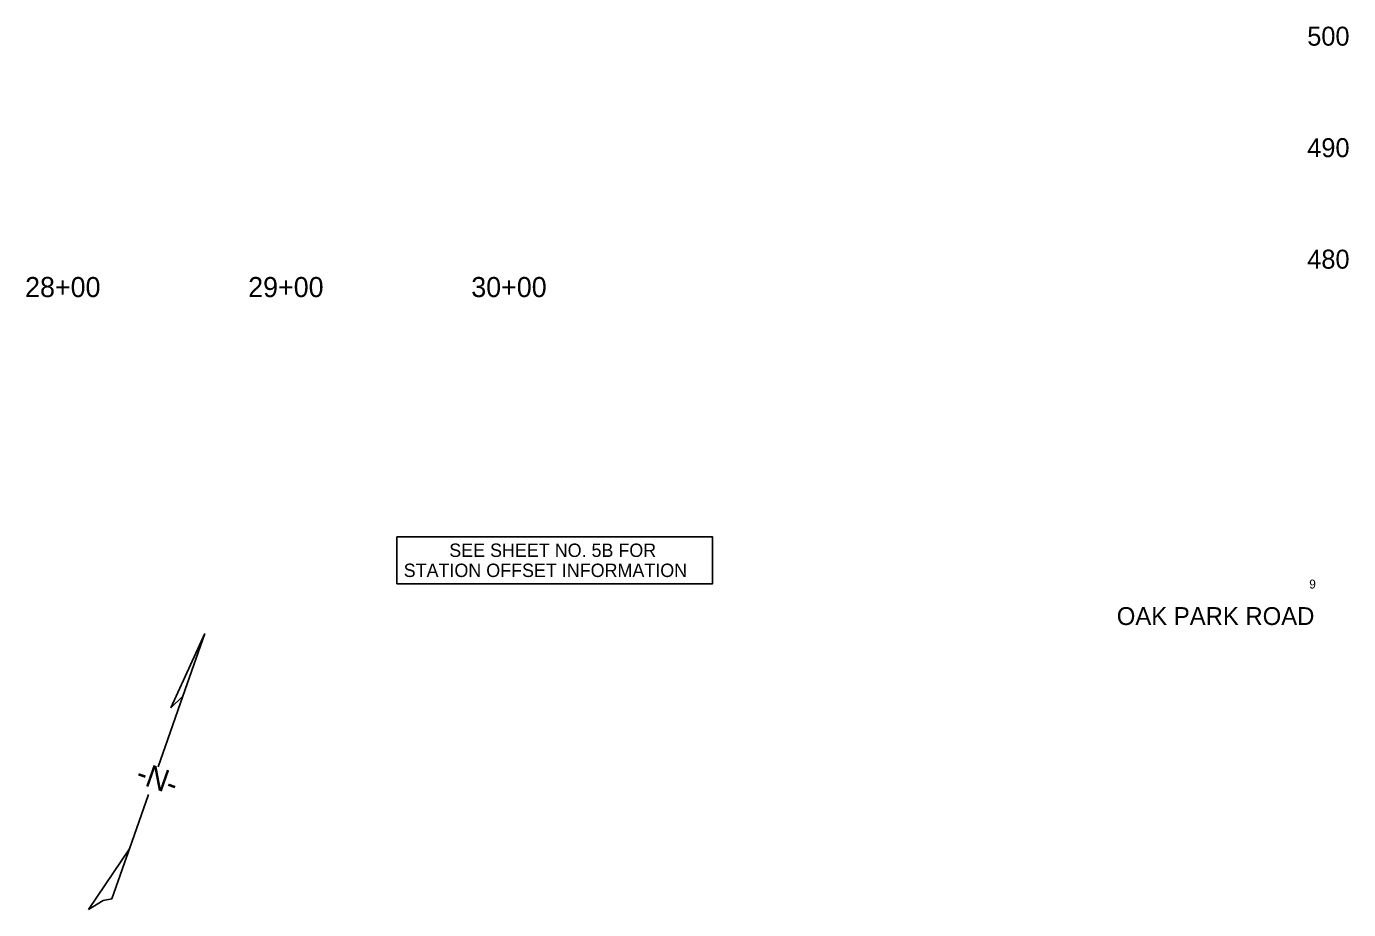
# Model space of a CAD drawing. Extents: x 1964377 to 1966966, y 1116414 to 1123213.
# Drawn here: x 1966357 to 1966950, y 1120739 to 1121135 of the extents above; entities that cross this region are included whole.
import ezdxf

# ---------------------------------------------------------------- set-up
doc = ezdxf.new("R2010")
doc.units = 0
for name, color, linetype in [('RD_DDB_Profile_Elev', 7, 'Continuous'), ('RD_DDB_StaTX', 7, 'Continuous'), ('RD_EX_Misc', 7, 'Continuous'), ('RD_SHT_TX', 7, 'Continuous'), ('RD_TX_StaOff', 7, 'Continuous')]:
    doc.layers.add(name, color=color, linetype=linetype)

msp = doc.modelspace()

# ---------------------------------------------------------------- linework, layer by layer
at = {"layer": 'RD_EX_Misc'}
for p, q in [((1966422, 1120829.88), (1966437.16, 1120863.13)), ((1966437.16, 1120863.13), (1966427.38, 1120835.15)), ((1966427.38, 1120835.15), (1966420.59, 1120815.76)), ((1966427.38, 1120835.15), (1966422, 1120829.88)), ((1966420.59, 1120815.76), (1966416.26, 1120803.4)), ((1966411.94, 1120791.05), (1966403.39, 1120766.61)), ((1966385.12, 1120739.37), (1966403.39, 1120766.61)), ((1966402.09, 1120762.9), (1966395.54, 1120744.17)), ((1966403.39, 1120766.61), (1966402.09, 1120762.9))]:
    msp.add_line(p, q, dxfattribs=at)
msp.add_lwpolyline([(1966395.54, 1120744.17), (1966391.55, 1120743.51), (1966385.12, 1120739.37)], dxfattribs=at)
at = {"layer": 'RD_TX_StaOff'}
msp.add_lwpolyline([(1966523.26, 1120906.51), (1966664.8, 1120906.51), (1966664.8, 1120885.51), (1966523.26, 1120885.51)], close=True, dxfattribs=at)

# ---------------------------------------------------------------- texts
at = {"layer": 'RD_DDB_Profile_Elev'}
for s, p in [('500', (1966931.34, 1121126.8)), ('490', (1966931.34, 1121076.8)), ('480', (1966931.34, 1121026.8))]:
    msp.add_text(s, height=8.5, dxfattribs=at).set_placement(p)
at = {"layer": 'RD_DDB_StaTX'}
for s, p in [('28+00', (1966356.62, 1121014.05)), ('29+00', (1966456.62, 1121014.05)), ('30+00', (1966556.62, 1121014.05))]:
    msp.add_text(s, height=9, dxfattribs=at).set_placement(p)
at = {"layer": 'RD_EX_Misc'}
msp.add_text('-N-', height=10, rotation=340.71384, dxfattribs=at).set_placement((1966405.63, 1120796.59))
at = {"layer": 'RD_SHT_TX'}
for s, height, p in [('9', 4, (1966932.23, 1120883.35)), ('OAK PARK ROAD', 8, (1966845.97, 1120867))]:
    msp.add_text(s, height=height, dxfattribs=at).set_placement(p)
at = {"layer": 'RD_TX_StaOff'}
for s, p in [('SEE SHEET NO. 5B FOR', (1966546.76, 1120897.51)), ('STATION OFFSET INFORMATION', (1966526.34, 1120888.51))]:
    msp.add_text(s, height=6, dxfattribs=at).set_placement(p)

doc.saveas('drawing.dxf')
